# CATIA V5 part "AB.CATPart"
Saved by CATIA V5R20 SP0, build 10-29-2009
Part number: bielle 1
Bounding box of the stored display mesh (mm): x 0 to 20, y -80 to -10, z -5 to 15
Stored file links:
  C:\Users\Willy\Documents\ThinkMotion\1691\AB.CATPart
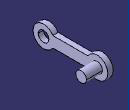
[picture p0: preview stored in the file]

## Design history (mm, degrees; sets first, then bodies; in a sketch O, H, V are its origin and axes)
Parameters
  `Longueur bièle` = 50 mm
Body1 (main body)
  Sketch1 on yz-plane, origin (0, 0, 0), H (0, 1, 0), V (0, 0, 1)
    line L1 (-70, 15) -> (-20, 15)
    line L2 (-20, -5) -> (-70, -5)
    point P2 (-20, 15)
    point P3 (-20, -5)
    point P4 (-70, -5)
    arc A1 centre (-20, 5) radius 10 from (-20, -5) to (-20, 15) ccw
    point P5 (-20, 5)
    arc A2 centre (-70, 5) radius 10 from (-70, 15) to (-70, -5) ccw
    point P6 (-70, 5)
    construction line L3 (-70, 30) -> (-70, -30)
    axis line L4 (-20, 35) -> (-20, -35)
    circle A3 centre (-70, 5) radius 5
    point P11 (-70, 0)
    circle A4 centre (-20, 5) radius 5
    length L1 = 50 {= `Longueur bièle`}
    radius A4 = 5
    radius A3 = 5
    distance L1 L2 = 20
    horizontal: L1 H, L2 H
    tangency: A2 L1
    vertical: L3 V, L4 V
    coincidence: P6 L3, P4 L3, P3 L4, P5 L4, P2 L4, A3 P11, P11 H
  Pad1: profile Sketch1, direction (1, 0, 0), length 5
  Sketch2 on end face of Pad1, origin (5, 0, 0), H (0, 1, 0), V (0, 0, 1)
    circle A1 centre (-20, 5) radius 5
    reference projected circle E1 centre (-20, 5) radius 5 from edge [end face of Pad1 | face of Pad1 from Sketch1.A4]
    coincidence: E1 A1
  Pad2: profile Sketch2, direction (-1, 0, 0), length 5, opposite side length 15
  Sketch3 on face of Pad2, origin (0, 0, 0), H (0, -1, 0), V (0, 0, 1)
    arc A1 centre (70, 5) radius 10 from (61.3397, 0) to (70, -5) ccw
    arc A2 centre (20, 5) radius 10 from (28.6603, 10) to (20, 15) ccw
    reference projected arc E1 centre (20, 5) radius 10 from (20, 15) to (20, -5) ccw from edge [start face of Pad1 | face of Pad1 from Sketch1.A1]
    reference projected arc E2 centre (70, 5) radius 10 from (70, -5) to (70, 15) ccw from edge [start face of Pad1 | face of Pad1 from Sketch1.A2]
    line L1 (70, 15) -> (20, 15)
    point P3 (70, 15)
    line L2 (20, -5) -> (70, -5)
    point P5 (20, -5)
    line L3 (61.3397, 0) -> (28.6603, 0)
    point P7 (61.3397, 0)
    line L4 (61.3397, 10) -> (28.6603, 10)
    arc A3 centre (70, 5) radius 10 from (70, 15) to (61.3397, 10) ccw
    arc A4 centre (20, 5) radius 10 from (20, -5) to (28.6603, 0) ccw
    coincidence: A2 E1, E2 A1, P3 A1, P5 A2, P7 H, A1 A3, A2 A4
    tangency: L1 A2, L2 A1
    horizontal: L3 H, L4 H
  Pocket1: profile Sketch3, direction (1, 0, 0), length 5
